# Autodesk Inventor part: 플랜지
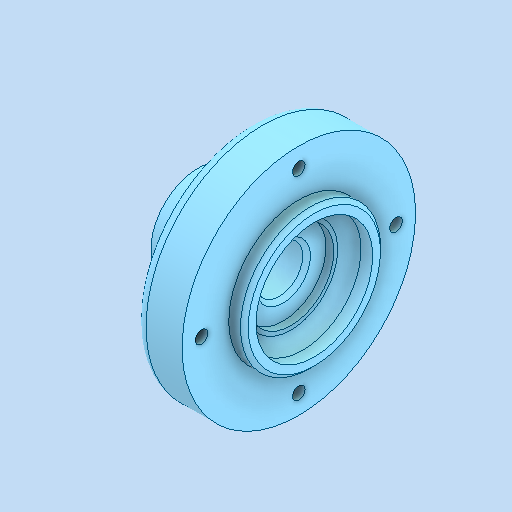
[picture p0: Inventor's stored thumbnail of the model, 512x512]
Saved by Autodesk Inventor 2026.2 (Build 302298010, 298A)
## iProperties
Created: 2026-03
Part Number: 플랜지
Material: 강철, 연강
Document SubType Name: Modeling
Designer: PC-2-06
Density: 7.85 g/cm^3
Appearance: 기본값
Author: jhkim
Sending System: Autodesk Inventor 2026
Preprocessor: ST-DEVELOPER v20.1
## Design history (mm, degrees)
feature "솔리드1"
node "솔리드2"
